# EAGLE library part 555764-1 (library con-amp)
AMP connector
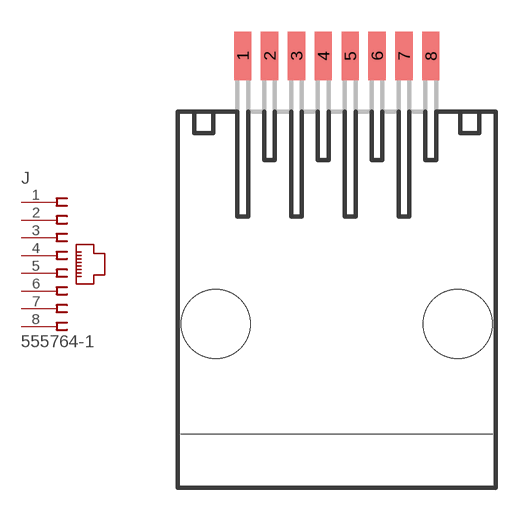
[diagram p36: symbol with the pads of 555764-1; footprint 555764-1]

Designator prefix J

## 555764-1 (MF: TYCO ELECTRONICS; MPN: 5555764-1; OC_FARNELL: 1522226; OC_NEWARK: 42K8766)  [555764-1]
1  1  pas
2  2  pas
3  3  pas
4  4  pas
5  5  pas
6  6  pas
7  7  pas
8  8  pas

## Footprint 555764-1 (pad centres in mm)
Modular Jack without Panel Stops
smd 0.813 x 2.286: 1 -4.445,11.533; 2 -3.175,11.533; 3 -1.905,11.533; 4 -0.635,11.533; 5 0.635,11.533; 6 1.905,11.533; 7 3.175,11.533; 8 4.445,11.533
hole 3.251 at -5.715,-1.143
hole 3.251 at 5.715,-1.143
